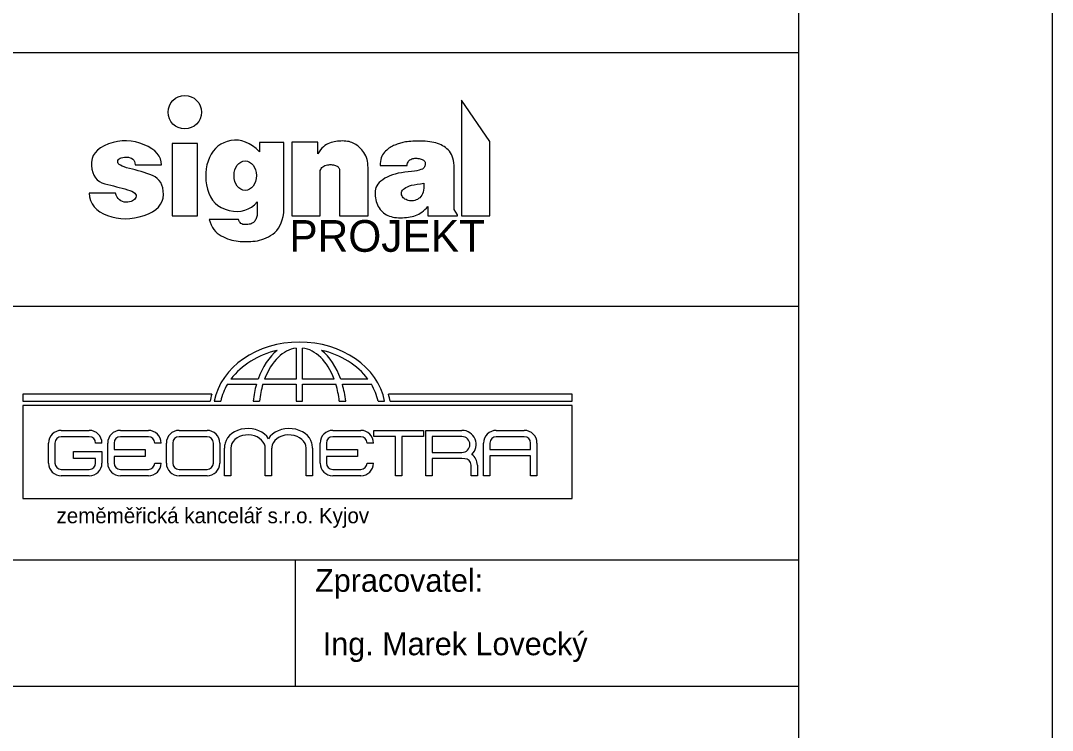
# Model space of a CAD drawing. Extents: x 1983 to 3683, y -4684 to -4239.
# Drawn here: x 2856.3 to 2937.6, y -4584.5 to -4528.5 of the extents above; entities that cross this region are included whole.
import ezdxf

# ---------------------------------------------------------------- set-up
doc = ezdxf.new("R2010")
doc.units = 0
for name, color, linetype in [('Default', 7, 'Continuous'), ('Komunikace', 7, 'Continuous'), ('Křížky', 7, 'Continuous'), ('Svazek obcí-chráničky', 7, 'Continuous'), ('Vrstva 51', 7, 'Continuous')]:
    doc.layers.add(name, color=color, linetype=linetype)

msp = doc.modelspace()

# ---------------------------------------------------------------- linework, layer by layer
at = {"layer": 'Default'}
msp.add_lwpolyline([(2727.602, -4683.032), (2937.602, -4683.032), (2937.602, -4386.032), (2727.602, -4386.032)], close=True, dxfattribs=at)
at = {"layer": 'Komunikace'}
for points in [[(2893.266, -4543.911), (2893.266, -4538.071), (2891.026, -4534.791), (2891.026, -4543.911), (2893.266, -4543.911)], [(2864.538, -4544.146), (2864.9, -4544.13), (2865.266, -4544.082), (2865.637, -4544.003), (2866.013, -4543.893), (2866.368, -4543.757), (2866.676, -4543.6), (2866.937, -4543.424), (2867.151, -4543.228), (2867.318, -4543.013), (2867.439, -4542.777), (2867.512, -4542.521), (2867.539, -4542.245), (2867.528, -4541.971), (2867.49, -4541.722), (2867.424, -4541.498), (2867.33, -4541.299), (2867.209, -4541.124), (2867.059, -4540.974), (2866.882, -4540.849), (2866.678, -4540.748), (2866.458, -4540.662), (2866.236, -4540.58), (2866.012, -4540.503), (2865.786, -4540.43), (2865.557, -4540.361), (2865.326, -4540.297), (2865.092, -4540.237), (2864.857, -4540.182), (2864.635, -4540.127), (2864.444, -4540.068), (2864.283, -4540.005), (2864.153, -4539.938), (2864.053, -4539.867), (2863.983, -4539.792), (2863.944, -4539.712), (2863.936, -4539.629), (2863.952, -4539.55), (2863.989, -4539.481), (2864.045, -4539.423), (2864.121, -4539.376), (2864.217, -4539.339), (2864.332, -4539.314), (2864.468, -4539.299), (2864.623, -4539.296), (2864.778, -4539.306), (2864.914, -4539.336), (2865.029, -4539.383), (2865.123, -4539.449), (2865.198, -4539.532), (2865.253, -4539.635), (2865.287, -4539.755), (2865.302, -4539.894), (2867.381, -4539.894), (2867.361, -4539.652), (2867.299, -4539.422), (2867.194, -4539.205), (2867.046, -4539.001), (2866.856, -4538.809), (2866.622, -4538.631), (2866.345, -4538.465), (2866.026, -4538.311), (2865.684, -4538.182), (2865.339, -4538.087), (2864.991, -4538.027), (2864.641, -4538.002), (2864.288, -4538.012), (2863.932, -4538.057), (2863.574, -4538.137), (2863.213, -4538.252), (2862.875, -4538.394), (2862.586, -4538.557), (2862.345, -4538.74), (2862.153, -4538.944), (2862.009, -4539.168), (2861.915, -4539.413), (2861.868, -4539.679), (2861.871, -4539.965), (2861.91, -4540.246), (2861.976, -4540.498), (2862.069, -4540.72), (2862.187, -4540.913), (2862.332, -4541.076), (2862.503, -4541.21), (2862.7, -4541.315), (2862.923, -4541.389), (2863.158, -4541.449), (2863.389, -4541.509), (2863.617, -4541.568), (2863.841, -4541.627), (2864.061, -4541.686), (2864.278, -4541.744), (2864.491, -4541.802), (2864.701, -4541.86), (2864.893, -4541.92), (2865.054, -4541.984), (2865.185, -4542.053), (2865.284, -4542.126), (2865.353, -4542.204), (2865.391, -4542.287), (2865.398, -4542.374), (2865.374, -4542.465), (2865.327, -4542.553), (2865.266, -4542.629), (2865.191, -4542.694), (2865.101, -4542.747), (2864.997, -4542.789), (2864.878, -4542.819), (2864.745, -4542.837), (2864.598, -4542.844), (2864.45, -4542.833), (2864.314, -4542.8), (2864.19, -4542.744), (2864.079, -4542.666), (2863.98, -4542.565), (2863.894, -4542.441), (2863.82, -4542.294), (2863.758, -4542.126), (2861.678, -4542.126), (2861.722, -4542.433), (2861.805, -4542.715), (2861.928, -4542.973), (2862.091, -4543.206), (2862.293, -4543.416), (2862.535, -4543.601), (2862.816, -4543.762), (2863.137, -4543.899), (2863.48, -4544.008), (2863.828, -4544.085), (2864.181, -4544.131), (2864.538, -4544.146)], [(2874.086, -4545.954), (2874.254, -4545.95), (2874.424, -4545.941), (2874.596, -4545.928), (2874.77, -4545.91), (2874.944, -4545.883), (2875.118, -4545.844), (2875.292, -4545.793), (2875.465, -4545.729), (2875.638, -4545.654), (2875.811, -4545.566), (2875.984, -4545.466), (2876.156, -4545.354), (2876.32, -4545.225), (2876.469, -4545.072), (2876.601, -4544.896), (2876.718, -4544.698), (2876.819, -4544.476), (2876.904, -4544.231), (2876.973, -4543.963), (2877.026, -4543.671), (2877.026, -4538.151), (2875.106, -4538.151), (2875.106, -4538.871), (2874.84, -4538.617), (2874.57, -4538.404), (2874.295, -4538.232), (2874.016, -4538.101), (2873.733, -4538.011), (2873.446, -4537.962), (2873.154, -4537.954), (2872.858, -4537.988), (2872.571, -4538.056), (2872.306, -4538.153), (2872.062, -4538.278), (2871.84, -4538.432), (2871.64, -4538.614), (2871.462, -4538.825), (2871.306, -4539.065), (2871.171, -4539.333), (2871.06, -4539.619), (2870.975, -4539.912), (2870.916, -4540.212), (2870.883, -4540.519), (2870.876, -4540.834), (2870.895, -4541.155), (2870.94, -4541.484), (2871.011, -4541.82), (2871.111, -4542.144), (2871.243, -4542.434), (2871.409, -4542.692), (2871.607, -4542.918), (2871.838, -4543.11), (2872.101, -4543.271), (2872.397, -4543.398), (2872.726, -4543.493), (2873.062, -4543.551), (2873.381, -4543.568), (2873.681, -4543.545), (2873.964, -4543.481), (2874.229, -4543.376), (2874.477, -4543.23), (2874.707, -4543.044), (2874.918, -4542.817), (2874.918, -4543.894), (2874.9, -4543.982), (2874.877, -4544.063), (2874.849, -4544.139), (2874.817, -4544.209), (2874.781, -4544.274), (2874.74, -4544.333), (2874.694, -4544.386), (2874.644, -4544.433), (2874.588, -4544.475), (2874.526, -4544.511), (2874.456, -4544.542), (2874.379, -4544.567), (2874.295, -4544.588), (2874.204, -4544.602), (2874.106, -4544.612), (2874.001, -4544.616), (2873.897, -4544.61), (2873.804, -4544.592), (2873.72, -4544.56), (2873.647, -4544.515), (2873.584, -4544.456), (2873.532, -4544.385), (2873.489, -4544.3), (2873.457, -4544.202), (2871.15, -4544.202), (2871.219, -4544.429), (2871.302, -4544.638), (2871.399, -4544.828), (2871.51, -4545), (2871.635, -4545.152), (2871.773, -4545.286), (2871.926, -4545.402), (2872.092, -4545.498), (2872.264, -4545.581), (2872.435, -4545.655), (2872.604, -4545.721), (2872.772, -4545.778), (2872.938, -4545.826), (2873.103, -4545.866), (2873.266, -4545.897), (2873.428, -4545.92), (2873.59, -4545.935), (2873.753, -4545.946), (2873.919, -4545.952), (2874.086, -4545.954)], [(2883.666, -4543.911), (2883.666, -4540.111), (2883.663, -4539.942), (2883.649, -4539.778), (2883.624, -4539.622), (2883.589, -4539.472), (2883.543, -4539.328), (2883.486, -4539.191), (2883.418, -4539.061), (2883.339, -4538.937), (2883.254, -4538.821), (2883.167, -4538.713), (2883.078, -4538.613), (2882.987, -4538.521), (2882.894, -4538.438), (2882.799, -4538.363), (2882.702, -4538.296), (2882.603, -4538.237), (2882.501, -4538.186), (2882.395, -4538.141), (2882.284, -4538.104), (2882.169, -4538.073), (2882.049, -4538.05), (2881.926, -4538.033), (2881.798, -4538.024), (2881.666, -4538.021), (2881.532, -4538.024), (2881.399, -4538.032), (2881.268, -4538.045), (2881.138, -4538.063), (2881.009, -4538.086), (2880.881, -4538.114), (2880.754, -4538.147), (2880.629, -4538.184), (2880.505, -4538.233), (2880.384, -4538.297), (2880.265, -4538.379), (2880.149, -4538.476), (2880.034, -4538.59), (2879.923, -4538.721), (2879.813, -4538.868), (2879.706, -4539.031), (2879.706, -4538.111), (2877.666, -4538.111), (2877.666, -4543.911), (2879.906, -4543.911), (2879.906, -4540.351), (2879.941, -4540.26), (2879.985, -4540.18), (2880.039, -4540.109), (2880.104, -4540.048), (2880.178, -4539.996), (2880.262, -4539.955), (2880.356, -4539.924), (2880.46, -4539.903), (2880.566, -4539.89), (2880.666, -4539.884), (2880.762, -4539.883), (2880.852, -4539.888), (2880.937, -4539.9), (2881.017, -4539.917), (2881.091, -4539.941), (2881.16, -4539.971), (2881.223, -4540.005), (2881.277, -4540.044), (2881.322, -4540.086), (2881.36, -4540.131), (2881.389, -4540.181), (2881.41, -4540.234), (2881.422, -4540.291), (2881.426, -4540.351), (2881.426, -4543.911), (2883.666, -4543.911)], [(2886.229, -4544.076), (2886.391, -4544.073), (2886.548, -4544.064), (2886.702, -4544.05), (2886.851, -4544.03), (2886.995, -4544.004), (2887.135, -4543.972), (2887.271, -4543.935), (2887.403, -4543.892), (2887.532, -4543.841), (2887.659, -4543.779), (2887.784, -4543.707), (2887.908, -4543.625), (2888.03, -4543.532), (2888.15, -4543.429), (2888.269, -4543.315), (2888.386, -4543.191), (2888.386, -4543.911), (2890.706, -4543.911), (2890.706, -4543.831), (2890.466, -4543.431), (2890.466, -4539.951), (2890.44, -4539.747), (2890.404, -4539.557), (2890.359, -4539.381), (2890.304, -4539.22), (2890.239, -4539.073), (2890.165, -4538.941), (2890.082, -4538.823), (2889.989, -4538.72), (2889.888, -4538.627), (2889.78, -4538.541), (2889.667, -4538.462), (2889.547, -4538.39), (2889.421, -4538.325), (2889.288, -4538.267), (2889.15, -4538.216), (2889.005, -4538.172), (2888.853, -4538.134), (2888.694, -4538.102), (2888.527, -4538.075), (2888.354, -4538.055), (2888.173, -4538.04), (2887.985, -4538.03), (2887.79, -4538.027), (2887.588, -4538.029), (2887.389, -4538.035), (2887.205, -4538.043), (2887.036, -4538.054), (2886.881, -4538.066), (2886.741, -4538.081), (2886.616, -4538.099), (2886.506, -4538.118), (2886.41, -4538.14), (2886.322, -4538.163), (2886.232, -4538.189), (2886.142, -4538.217), (2886.051, -4538.246), (2885.96, -4538.278), (2885.868, -4538.311), (2885.775, -4538.347), (2885.682, -4538.384), (2885.589, -4538.426), (2885.496, -4538.474), (2885.405, -4538.529), (2885.315, -4538.592), (2885.226, -4538.661), (2885.138, -4538.736), (2885.05, -4538.819), (2884.964, -4538.909), (2884.884, -4539.006), (2884.815, -4539.113), (2884.756, -4539.229), (2884.709, -4539.355), (2884.672, -4539.49), (2884.646, -4539.635), (2884.631, -4539.788), (2884.626, -4539.951), (2886.746, -4539.951), (2886.762, -4539.855), (2886.786, -4539.768), (2886.819, -4539.69), (2886.86, -4539.621), (2886.91, -4539.561), (2886.969, -4539.511), (2887.036, -4539.469), (2887.112, -4539.437), (2887.193, -4539.413), (2887.274, -4539.395), (2887.355, -4539.384), (2887.437, -4539.379), (2887.52, -4539.381), (2887.603, -4539.389), (2887.687, -4539.404), (2887.771, -4539.425), (2887.851, -4539.451), (2887.923, -4539.478), (2887.985, -4539.508), (2888.039, -4539.54), (2888.084, -4539.574), (2888.121, -4539.611), (2888.148, -4539.649), (2888.167, -4539.69), (2888.178, -4539.733), (2888.183, -4539.778), (2888.182, -4539.827), (2888.175, -4539.878), (2888.161, -4539.933), (2888.141, -4539.99), (2888.115, -4540.049), (2888.082, -4540.112), (2888.032, -4540.173), (2887.951, -4540.229), (2887.839, -4540.28), (2887.698, -4540.325), (2887.526, -4540.365), (2887.323, -4540.4), (2887.091, -4540.429), (2886.828, -4540.453), (2886.556, -4540.48), (2886.296, -4540.518), (2886.049, -4540.565), (2885.814, -4540.624), (2885.591, -4540.693), (2885.381, -4540.772), (2885.183, -4540.862), (2884.997, -4540.963), (2884.828, -4541.071), (2884.679, -4541.184), (2884.552, -4541.301), (2884.445, -4541.423), (2884.36, -4541.549), (2884.295, -4541.68), (2884.251, -4541.815), (2884.228, -4541.955), (2884.22, -4542.096), (2884.221, -4542.236), (2884.231, -4542.375), (2884.25, -4542.513), (2884.278, -4542.65), (2884.315, -4542.785), (2884.361, -4542.92), (2884.416, -4543.053), (2884.479, -4543.181), (2884.549, -4543.3), (2884.626, -4543.41), (2884.709, -4543.512), (2884.8, -4543.605), (2884.898, -4543.688), (2885.002, -4543.763), (2885.114, -4543.829), (2885.232, -4543.887), (2885.356, -4543.937), (2885.486, -4543.979), (2885.622, -4544.014), (2885.765, -4544.041), (2885.913, -4544.06), (2886.068, -4544.072), (2886.229, -4544.076)], [(2870.226, -4543.911), (2870.226, -4538.231), (2868.226, -4538.231), (2868.226, -4543.911), (2870.226, -4543.911)], [(2886.945, -4542.731), (2886.842, -4542.711), (2886.747, -4542.682), (2886.66, -4542.646), (2886.581, -4542.603), (2886.511, -4542.551), (2886.448, -4542.492), (2886.393, -4542.426), (2886.346, -4542.351), (2886.312, -4542.273), (2886.294, -4542.196), (2886.293, -4542.12), (2886.308, -4542.045), (2886.341, -4541.971), (2886.39, -4541.898), (2886.456, -4541.826), (2886.538, -4541.754), (2886.642, -4541.686), (2886.77, -4541.623), (2886.924, -4541.565), (2887.103, -4541.513), (2887.307, -4541.466), (2887.537, -4541.424), (2887.791, -4541.387), (2888.071, -4541.356), (2888.075, -4541.554), (2888.067, -4541.736), (2888.045, -4541.902), (2888.01, -4542.052), (2887.963, -4542.186), (2887.902, -4542.303), (2887.829, -4542.404), (2887.743, -4542.49), (2887.649, -4542.561), (2887.554, -4542.62), (2887.457, -4542.668), (2887.358, -4542.704), (2887.257, -4542.728), (2887.155, -4542.741), (2887.051, -4542.742), (2886.945, -4542.731)]]:
    msp.add_lwpolyline(points, dxfattribs=at)
msp.add_circle((2869.226, -4535.751), 1.32, dxfattribs=at)
msp.add_ellipse((2873.986, -4540.751), major_axis=(0, 1.16), ratio=0.758621, dxfattribs=at)
at = {"layer": 'Křížky'}
msp.add_lwpolyline([(2747.602, -4406.032), (2917.602, -4406.032), (2917.602, -4666.032), (2747.602, -4666.032)], close=True, dxfattribs=at)
at = {"layer": 'Svazek obcí-chráničky'}
for p, q in [((2877.997, -4554.345), (2877.997, -4556.791)), ((2878.504, -4556.791), (2878.504, -4554.343)), ((2875.003, -4556.791), (2872.858, -4556.791)), ((2877.997, -4556.791), (2875.52, -4556.791)), ((2880.998, -4556.791), (2878.504, -4556.791)), ((2883.66, -4556.791), (2881.515, -4556.791)), ((2872.583, -4557.202), (2874.871, -4557.202)), ((2875.381, -4557.202), (2877.997, -4557.202)), ((2877.997, -4557.202), (2877.997, -4558.523)), ((2878.504, -4558.523), (2878.504, -4557.202)), ((2878.504, -4557.202), (2881.138, -4557.202)), ((2881.648, -4557.202), (2883.935, -4557.202)), ((2871.352, -4557.991), (2856.472, -4557.991)), ((2856.472, -4557.991), (2856.472, -4558.523)), ((2899.75, -4557.991), (2885.272, -4557.991)), ((2899.75, -4558.523), (2899.75, -4557.991)), ((2899.749, -4558.867), (2856.466, -4558.867)), ((2856.466, -4558.867), (2856.466, -4566.205)), ((2856.472, -4558.523), (2871.215, -4558.523)), ((2871.54, -4558.523), (2872.057, -4558.523)), ((2874.614, -4558.523), (2875.114, -4558.523)), ((2877.997, -4558.523), (2878.504, -4558.523)), ((2881.405, -4558.523), (2881.905, -4558.523)), ((2884.461, -4558.523), (2884.978, -4558.523)), ((2885.41, -4558.523), (2899.75, -4558.523)), ((2899.749, -4566.205), (2899.749, -4558.867)), ((2859.491, -4560.833), (2861.701, -4560.833)), ((2864.147, -4560.833), (2866.358, -4560.833)), ((2868.771, -4560.833), (2870.981, -4560.833)), ((2880.889, -4560.833), (2883.1, -4560.833)), ((2888.227, -4560.833), (2891.071, -4560.833)), ((2893.775, -4560.833), (2895.986, -4560.833)), ((2861.701, -4561.332), (2859.491, -4561.332)), ((2866.358, -4561.332), (2864.147, -4561.332)), ((2870.981, -4561.332), (2868.771, -4561.332)), ((2883.1, -4561.332), (2880.889, -4561.332)), ((2885.832, -4564.415), (2885.832, -4561.32)), ((2886.336, -4561.32), (2886.336, -4564.415)), ((2891.071, -4561.322), (2888.731, -4561.322)), ((2888.731, -4561.322), (2888.731, -4562.572)), ((2895.986, -4561.332), (2893.775, -4561.332)), ((2858.493, -4563.417), (2858.493, -4561.831)), ((2858.992, -4561.831), (2858.992, -4563.417)), ((2862.699, -4561.831), (2862.2, -4561.831)), ((2863.149, -4563.417), (2863.149, -4561.831)), ((2863.648, -4561.831), (2863.648, -4562.342)), ((2863.648, -4562.342), (2866.091, -4562.342)), ((2866.091, -4562.342), (2866.091, -4562.886)), ((2867.355, -4561.831), (2866.857, -4561.831)), ((2867.773, -4563.417), (2867.773, -4561.831)), ((2868.272, -4561.831), (2868.272, -4563.417)), ((2871.481, -4563.417), (2871.481, -4561.831)), ((2871.979, -4561.831), (2871.979, -4563.417)), ((2872.352, -4564.415), (2872.352, -4562.23)), ((2872.852, -4562.23), (2872.852, -4564.415)), ((2875.572, -4564.415), (2875.572, -4562.23)), ((2876.072, -4562.23), (2876.072, -4564.415)), ((2878.791, -4564.415), (2878.791, -4562.23)), ((2879.291, -4562.23), (2879.291, -4564.415)), ((2879.892, -4563.417), (2879.892, -4561.831)), ((2880.39, -4561.831), (2880.39, -4562.342)), ((2880.39, -4562.342), (2882.833, -4562.342)), ((2882.833, -4562.342), (2882.833, -4562.886)), ((2884.098, -4561.831), (2883.599, -4561.831)), ((2892.777, -4564.415), (2892.777, -4561.831)), ((2893.276, -4561.831), (2893.276, -4562.34)), ((2893.276, -4562.34), (2896.485, -4562.34)), ((2896.485, -4562.34), (2896.485, -4561.831)), ((2896.983, -4561.831), (2896.983, -4564.415)), ((2860.466, -4563.039), (2860.466, -4562.494)), ((2860.466, -4562.494), (2862.699, -4562.494)), ((2862.2, -4563.039), (2860.466, -4563.039)), ((2862.2, -4563.417), (2862.2, -4563.039)), ((2862.699, -4562.494), (2862.699, -4563.417)), ((2866.091, -4562.886), (2863.648, -4562.886)), ((2863.648, -4562.886), (2863.648, -4563.417)), ((2882.833, -4562.886), (2880.39, -4562.886)), ((2880.39, -4562.886), (2880.39, -4563.417)), ((2888.731, -4562.572), (2891.071, -4562.572)), ((2891.071, -4563.061), (2888.731, -4563.061)), ((2891.285, -4563.064), (2891.071, -4563.061)), ((2896.485, -4562.843), (2893.276, -4562.843)), ((2893.276, -4562.843), (2893.276, -4564.415)), ((2896.485, -4564.415), (2896.485, -4562.843)), ((2859.491, -4563.916), (2861.701, -4563.916)), ((2864.147, -4563.916), (2866.358, -4563.916)), ((2866.857, -4563.417), (2867.355, -4563.417)), ((2868.771, -4563.916), (2870.981, -4563.916)), ((2880.889, -4563.916), (2883.1, -4563.916)), ((2883.599, -4563.417), (2884.098, -4563.417)), ((2891.784, -4564.415), (2891.784, -4563.564)), ((2892.283, -4563.564), (2892.283, -4564.415)), ((2861.701, -4564.415), (2859.491, -4564.415)), ((2866.358, -4564.415), (2864.147, -4564.415)), ((2870.981, -4564.415), (2868.771, -4564.415)), ((2872.852, -4564.415), (2872.352, -4564.415)), ((2876.072, -4564.415), (2875.572, -4564.415)), ((2879.291, -4564.415), (2878.791, -4564.415)), ((2883.1, -4564.415), (2880.889, -4564.415)), ((2886.336, -4564.415), (2885.832, -4564.415)), ((2892.283, -4564.415), (2891.784, -4564.415)), ((2893.276, -4564.415), (2892.777, -4564.415)), ((2896.983, -4564.415), (2896.485, -4564.415)), ((2856.466, -4566.205), (2899.749, -4566.205))]:
    msp.add_line(p, q, dxfattribs=at)
for points in [[(2885.832, -4561.32), (2884.134, -4561.32), (2884.134, -4560.833), (2888.048, -4560.833)], [(2888.048, -4560.833), (2888.048, -4561.32), (2886.336, -4561.32)], [(2888.731, -4563.061), (2888.731, -4564.415), (2888.227, -4564.415), (2888.227, -4560.833)]]:
    msp.add_lwpolyline(points, dxfattribs=at)
for centre, radius, start, end in [((2859.491, -4561.831), 0.998, 90, 180), ((2861.701, -4561.831), 0.998, 360, 90), ((2864.147, -4561.831), 0.998, 90, 180), ((2866.358, -4561.831), 0.998, 360, 90), ((2868.771, -4561.831), 0.998, 90, 180), ((2870.981, -4561.831), 0.998, 360, 90), ((2880.889, -4561.831), 0.998, 90, 180), ((2883.1, -4561.831), 0.998, 360, 90), ((2891.071, -4561.947), 1.114, 314.45734, 90), ((2893.775, -4561.831), 0.998, 90, 180), ((2895.986, -4561.831), 0.998, 360, 90), ((2859.491, -4561.831), 0.499, 90, 180), ((2861.701, -4561.831), 0.499, 0, 90), ((2864.147, -4561.831), 0.499, 90, 180), ((2866.358, -4561.831), 0.499, 0, 90), ((2868.771, -4561.831), 0.499, 90, 180), ((2870.981, -4561.831), 0.499, 0, 90), ((2880.889, -4561.831), 0.499, 90, 180), ((2883.1, -4561.831), 0.499, 0, 90), ((2891.071, -4561.947), 0.625, 270, 90), ((2893.775, -4561.831), 0.499, 90, 180), ((2895.986, -4561.831), 0.499, 0, 90), ((2874.289, -4562.28), 1.938, 166.96576, 178.52091), ((2874.617, -4562.294), 0.957, 3.86486, 22.41569), ((2877.305, -4562.352), 1.238, 162.61388, 174.3506), ((2877.354, -4562.28), 1.938, 1.47909, 13.03424), ((2891.285, -4563.564), 0.499, 0, 90), ((2891.285, -4563.564), 0.998, 360, 55.44734), ((2859.491, -4563.417), 0.998, 180, 270), ((2859.491, -4563.417), 0.499, 180, 270), ((2861.701, -4563.417), 0.998, 270, 0), ((2861.701, -4563.417), 0.499, 270, 0), ((2864.147, -4563.417), 0.998, 180, 270), ((2864.147, -4563.417), 0.499, 180, 270), ((2866.358, -4563.417), 0.998, 270, 0), ((2866.358, -4563.417), 0.499, 270, 0), ((2868.771, -4563.417), 0.998, 180, 270), ((2868.771, -4563.417), 0.499, 180, 270), ((2870.981, -4563.417), 0.998, 270, 0), ((2870.981, -4563.417), 0.499, 270, 0), ((2880.889, -4563.417), 0.998, 180, 270), ((2880.889, -4563.417), 0.499, 180, 270), ((2883.1, -4563.417), 0.998, 270, 0), ((2883.1, -4563.417), 0.499, 270, 0)]:
    msp.add_arc(centre, radius, start, end, dxfattribs=at)
for centre, major_axis, ratio, start_param, end_param in [((2878.259, -4559.395), (-6.804, 0), 0.811768, 3.300239, 6.124539), ((2878.259, -4559.395), (0, 5.067), 0.630136, 0.08224, 1.030995), ((2878.259, -4559.395), (0, 5.067), 0.630136, 5.252191, 6.206521), ((2878.259, -4559.395), (-6.296, 0), 0.804826, 4.992897, 5.743383), ((2878.259, -4559.395), (0, 5.524), 0.668443, 0.491666, 1.079789), ((2878.259, -4559.395), (0, 5.524), 0.668443, 5.203397, 5.79152), ((2878.259, -4559.395), (-6.296, 0), 0.804826, 3.681394, 4.431881), ((2878.259, -4559.395), (-6.296, 0), 0.804826, 5.835664, 6.110118), ((2878.259, -4559.395), (0, 5.524), 0.668443, 1.16256, 1.41215), ((2878.259, -4559.395), (0, 5.067), 0.630136, 1.123275, 1.397729), ((2878.259, -4559.395), (0, 5.067), 0.630136, 4.885456, 5.159911), ((2878.259, -4559.395), (0, 5.524), 0.668443, 4.871035, 5.120625), ((2878.259, -4559.395), (-6.296, 0), 0.804826, 3.31466, 3.589114), ((2877.933, -4559.395), (-6.804, 0), 0.811768, 6.026233, 6.124539), ((2878.691, -4559.395), (-6.804, 0), 0.811768, 3.300239, 3.398545), ((2874.181, -4562.074), (1.805, 0), 0.766187, 0.429647, 2.97338), ((2877.462, -4562.074), (-1.805, 0), 0.766187, 3.309805, 5.853538), ((2874.206, -4562.23), (1.354, 0), 0.766187, 0.29376, 3.141593), ((2877.437, -4562.23), (-1.354, 0), 0.766187, 3.141593, 6.041607)]:
    msp.add_ellipse(centre, major_axis=major_axis, ratio=ratio, start_param=start_param, end_param=end_param, dxfattribs=at)
at = {"layer": 'Vrstva 51'}
for p, q in [((2747.602, -4551.032), (2917.602, -4551.032)), ((2747.602, -4571.032), (2917.602, -4571.032)), ((2877.952, -4581.032), (2877.952, -4571.032))]:
    msp.add_line(p, q, dxfattribs=at)
msp.add_lwpolyline([(2747.602, -4531.032), (2917.602, -4531.032), (2917.602, -4581.032), (2747.602, -4581.032)], close=True, dxfattribs=at)

# ---------------------------------------------------------------- texts
at = {"layer": 'Komunikace'}
msp.add_text('PROJEKT', height=2.5, dxfattribs=at).set_placement((2877.467, -4546.755))
at = {"layer": 'Svazek obcí-chráničky'}
msp.add_text('zeměměřická kancelář s.r.o. Kyjov', height=1.20984, dxfattribs=at).set_placement((2859.117, -4568.154))
at = {"layer": 'Vrstva 51'}
for s, p in [('Zpracovatel:', (2879.498, -4573.559)), ('Ing. Marek Lovecký', (2880.099, -4578.559))]:
    msp.add_text(s, height=1.8, dxfattribs=at).set_placement(p)

doc.saveas('drawing.dxf')
